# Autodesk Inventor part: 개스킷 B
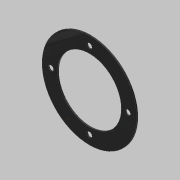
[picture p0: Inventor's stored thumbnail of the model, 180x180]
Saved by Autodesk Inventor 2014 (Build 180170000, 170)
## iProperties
Created: 2019-10
Part Number: 개스킷 B
Material: 고무
Document SubType Name: Modeling
Designer: mduedu
Density: 1 g/cm^3
Appearance: Rubber - Black - Version 1.1
Author: mduedu
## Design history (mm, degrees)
sketch "스케치1"
  geometry: C1 r 40 at (0, 0); C2 r 27 at (0, 0); 1 further point
  constraints: 2 centre point, 2 coincident
  dimensions: "d0" = 80 diameter of C1; "d1" = 54 diameter of C2
extrude "돌출1" new body sketch "스케치1" distance "d2" = 1; taper "d3" = 0 deg
sketch "스케치2" dims "d4" = 65
  geometry: C1 r 2.25 at (0, 32.5); 2 further points
  constraints: 2 vertical alignment, 1 centre point, 1 coincident, 2 other
  dimensions: "d5" = 4.5 diameter of C1
extrude "돌출2" cut sketch "스케치2" stored distance "d6" = 1; taper "d7" = 0 deg
node "솔리드1"
pattern_circular "원형 패턴1" dims angle "d9" = 360 deg
